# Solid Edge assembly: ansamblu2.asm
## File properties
Author: Ionut
Template: Normal.asm
Last saved by: Ionut
Revision: 9
Application: Solid Edge
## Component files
cadru.par
cupla.par
tija.par
bolt.par
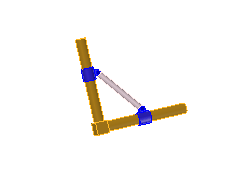
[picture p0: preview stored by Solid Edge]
